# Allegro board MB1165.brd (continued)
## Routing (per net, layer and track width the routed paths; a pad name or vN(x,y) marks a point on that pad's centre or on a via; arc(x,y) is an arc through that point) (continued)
VBUS_FS1: length 209.7
  TOP w0.203: D5.B3 8.68,100.12 9.27,100.71 v1(9.27,101.47)
  TOP w0.381: CN13.1 5.36,98.4 v1(6.73,97.03)
  TOP w0.508: CN6.54 114.2,122.94 112.88,124.26 v1(111.89,124.26) ; v1(6.73,97.03) 6.73,97 7.24,96.49 C49.1 8.31,93.29 U11.1 ; v1(9.27,101.47) 10.16,102.36 10.16,102.87 v1(10.67,103.38) R100.1 ; D9.1 v1(25.91,81.03)
  L3_SIG w0.508: JP14.3 3.18,74.17 3.18,76.35 5.16,78.33 5.16,81.48 6.1,82.42 6.1,94.74 6.73,95.38 v1(6.73,97.03) 6.73,97.69 6.02,98.4 6.02,100.51 6.99,101.47 v1(9.27,101.47) ; v1(111.89,124.26) 111.89,126.75 110.62,128.02 v1(108.08,128.02) 107.95,127.89 107.95,127.13 108.97,126.11 108.97,123.95 106.43,121.41 98.98,121.41 96.84,119.27 60.69,119.27 58.8,121.16 48.51,121.16 44.7,117.35 44.7,112.52 36.96,104.78 36.96,103.48 32.79,99.31 26.42,99.31 24.64,101.09 22.35,101.09 19.68,103.76 11.05,103.76 v1(10.67,103.38)
  BOTTOM w0.508: JP14.3 5.84,71.5 8.94,71.5 10.54,73.1 10.54,77.72 13.21,80.39 14.61,80.39 15.24,81.03 v1(25.91,81.03) ; v1(108.08,128.02) R253.2
VBUS_FS2: length 125.7
  TOP w0.254: D6.B3 8.81,85.77 9.83,86.79 v1(9.83,87.76)
  TOP w0.381: 5.36,84.04 CN14.1
  TOP w0.508: D10.1 v1(26.03,78.99) ; v1(39.52,127.48) 39.05,127.01 39.05,126.56 36.22,123.72 26.09,123.72 v1(25.86,123.49) ; v1(6.1,81.15) 7.24,81.15 R126.1 7.37,82.55 5.87,84.04 5.36,84.04 ; SB14.1 v1(15.88,114.05)
  L3_SIG w0.508: v1(6.1,81.15) 7.24,82.3 7.24,83.95 8,84.71 8,85.09 9.83,86.92 v1(9.83,87.76)
  BOTTOM w0.508: v1(25.86,123.49) 25.86,122.5 21.84,118.49 17.48,118.49 15.88,116.89 v1(15.88,114.05) 14.73,112.9 14.73,110.49 11.81,107.57 10.67,107.57 9.91,106.81 9.91,87.83 v1(9.83,87.76) ; v1(26.03,78.99) 26.16,78.99 26.75,78.41 26.75,74.61 27.18,74.18 27.18,73.65 26.75,73.22 26.75,73.1 25.91,72.26 25.15,72.26 22.35,69.47 19.79,69.47 19.28,68.96 5.84,68.96 JP14.5 2.67,72.14 2.67,77.72 v1(6.1,81.15) ; R255.1 39.55,127.51 v1(39.52,127.48)
VBUS_HS: length 75.8
  TOP w0.203: D3.A1 7.75,116.13 v1(7.37,115.75)
  TOP w0.381: CN8.1 6.96,111.86 L2.2
  TOP w0.508: L2.2 v1(7.37,113.18) ; D8.1 v1(25.93,83.06)
  BOTTOM w0.508: v1(25.93,83.06) 14.22,83.06 9.27,78.11 9.27,75.06 8.26,74.04 5.84,74.04 JP14.1 4.57,77.98 7.16,80.56 7.16,82.63 5.97,83.82 5.97,100.58 7.37,101.98 v1(7.37,113.18) v1(7.37,115.75)
VDD_MCU: length 46.8
  TOP w0.381: v5(79.61,140.09) U4.G5 ; v5(81.21,135.29) U4.E10 ; U4.H5 v5(78.01,139.29) ; U4.L9 v5(75.61,136.09) ; U4.F4 v5(80.41,140.89) ; U4.E8 v5(81.21,136.89) U4.E9 ; U4.E7 v5(80.41,138.49) ; U4.L10 v5(75.61,135.29) ; U4.J11 v5(77.21,134.49) U4.K11 ; U4.L8 v5(76.41,136.89) ; U4.H11 v5(78.01,134.49) ; v5(75.61,138.49) U4.L7 ; U4.F5 v5(80.41,140.09) ; U4.J5 v5(77.22,139.29) ; U4.F11 v5(80.41,134.49) ; v5(79.61,134.49) U4.G11 ; U4.K5 v5(76.41,140.09)
  TOP w0.508: v1(88.77,132.08) 89.03,131.83 C26.2 ; C28.2 60.33,130.81 v1(60.2,130.68)
  BOTTOM w0.381: v5(86.11,135.66) 86.08,135.64 85.78,135.64 85.27,136.14 C133.1 ; v5(78.01,139.29) 78.17,139.45 C121.1 ; C111.1 81.66,143.76 v5(81.28,143.38) ; v5(76.41,136.89) 76.45,136.93 C127.1 ; C126.1 80.77,138.12 v5(80.41,138.49) ; v5(79.61,140.09) 79.11,140.59 C117.1 ; C135.1 72.64,135.38 72.14,134.87 v5(72.01,134.87) ; C125.1 81.92,137.59 v5(81.21,136.89) ; C107.2 86.49,149.1 v1(86.94,149.56) ; v5(81.21,135.29) 80.77,135.73 C131.1 ; v3(77.93,145.01) 77.93,144.88 77.9,144.86 77.9,144.58 78.02,144.47 78.02,144.23 C112.1 ; C129.1 72.64,137.8 v5(72.06,138.38) 72.62,138.94 C120.1 ; v1(85.88,137.85) 85.85,137.85 85.82,137.81 85.24,137.81 C124.1 ; C132.1 75.79,136.27 v5(75.61,136.09) ; v5(78.01,134.49) 78.26,134.24 C136.1 ; C134.1 78.77,135.33 v5(79.61,134.49) ; C128.1 75.31,138.19 v5(75.61,138.49) ; C119.1 85.05,140.54 85.43,140.54 v5(85.72,140.84)
  BOTTOM w0.508: JP2.2 61.09,150.57 ; JP2.2 60.12,149.61 ; JP2.2 62.05,149.61 ; JP2.2 61.09,148.64 ; 61.09,143.64 61.09,144.6 ; 61.09,143.64 61.93,143.64 ; 61.09,143.64 61.09,142.67 ; 61.09,143.64 60.25,143.64 ; 61.85,140.49 L7.1 ; L7.1 61.85,141.71 ; L7.1 61.2,141.1 ; 61.09,146.3 61.09,147.27 ; 61.09,146.3 61.09,145.34 ; 61.09,146.3 61.93,146.3 ; 61.09,146.3 60.25,146.3 ; C130.2 v1(59.82,137.41) ; C118.1 59.94,141.58 ; C118.1 60.43,141.1 ; C118.1 59.94,140.61
  vias: v1(60.2,139.95) v1(60.2,139.32) v1(60.96,139.95) v1(60.96,139.32) v1(61.72,139.95) v1(61.72,139.32)
VDDA: length 15.6
  TOP w0.381: v5(72.14,143.05) 72.14,143.01 72.26,142.89 U4.R1
  TOP w0.508: v3(68.07,143.64) 67.06,143.64 R33.1
  BOTTOM w0.381: v5(72.14,143.05) 72.52,142.67 C116.2
  BOTTOM w0.508: L7.2 TP9.1 C114.1 v3(68.07,143.64) 68.71,143.64 69.29,143.05 v5(72.14,143.05)
A0: length 136.3
  TOP w0.102: 78.84,107.95 77.47,106.58 77.47,105.81 U9.E2 ; v5(69.74,73.28) 69.74,73.52 69.22,74.03 U16.A3 ; U15.G8 91.83,71.77 v5(91.44,71.37)
  TOP w0.127: CN11.14 v3(103.38,109.78) ; v4(78.89,108.08) 78.84,108.03 78.84,107.95
  L3_SIG w0.102: v3(103.38,109.78) 102.9,109.3 101.35,109.3 98.48,106.43 80.17,106.43 78.89,107.71 v4(78.89,108.08) ; v5(91.44,71.37) 91.44,71.63 89.83,73.23 84.28,73.23 83.59,72.54 79.57,72.54 v1(79.29,72.82) 79.21,72.9 78.81,72.9 78.61,72.69 78.41,72.69 78.2,72.9 78,72.9 77.8,72.69 77.59,72.69 77.39,72.9 77.19,72.9 76.98,72.69 76.78,72.69 76.58,72.9 76.38,72.9 76.17,72.69 75.97,72.69 75.77,72.9 75.56,72.9 75.36,72.69 75.16,72.69 74.95,72.9 74.75,72.9 74.55,72.69 74.34,72.69 74.14,72.9 73.94,72.9 73.73,72.69 73.53,72.69 73.33,72.9 73.12,72.9 72.92,72.69 72.72,72.69 72.51,72.9 72.31,72.9 72.11,72.69 71.9,72.69 71.7,72.9 71.42,72.9 71.32,72.8 70.21,72.8 69.74,73.26 v5(69.74,73.28)
  BOTTOM w0.127: v3(103.38,109.78) 102.82,109.22 101.73,109.22 95.15,115.8 95.15,120.12 95.02,120.24 94.23,120.24 94.11,120.37 94.11,137.57 92.74,138.94 90.93,138.94 R236.2 ; v4(78.89,108.08) 78.89,105.13 79.88,104.14 79.88,101.6 80.52,100.97 81.92,100.97 82.82,100.06 82.82,99.7 82.8,99.69 82.8,99.64 80.8,97.64 80.8,94.65 80.53,94.39 80.53,76.06 79.5,75.03 79.5,74.14 79.29,73.93 v1(79.29,72.82)
A1: length 137.8
  TOP w0.102: v5(69.2,73.28) 69.2,73.29 U16.A4 ; 79.88,107.95 78.51,106.58 78.51,105.77 U9.D2 ; U15.G9 91.44,70.55 v5(91.44,70.48)
  TOP w0.127: CN11.12 v3(103.38,111.05) ; v4(80.26,108.64) 79.93,108.31 79.93,108 79.88,107.95
  L3_SIG w0.102: v4(80.26,108.64) 80.26,108.46 81.53,107.19 97.89,107.19 101.22,110.52 102.84,110.52 v3(103.38,111.05) ; v5(91.44,70.48) 91.01,70.91 91.01,71.52 89.6,72.93 84.49,72.93 83.77,72.21 80.49,72.21 v1(80.39,72.11) 80.29,72.11 80.26,72.14 79.5,72.14 79.25,72.39 69.96,72.39 69.2,73.15 v5(69.2,73.28)
  BOTTOM w0.127: v3(103.38,111.05) 103.38,110.95 102.9,110.46 101.83,110.46 96.06,116.23 96.06,121.28 94.87,122.48 94.87,139.48 93,141.35 91.69,141.35 R232.2 ; v4(80.26,108.64) 80.26,108.43 83.03,105.66 83.03,104.17 85.09,102.11 85.09,86.23 84.96,86.11 83.11,86.11 82.98,85.98 82.98,78.76 82.36,78.14 82.36,75.73 81.41,74.78 81.41,73.79 80.39,72.77 v1(80.39,72.11)
A2: length 134.8
  TOP w0.102: U15.F7 92.08,73.15 v5(91.44,73.15) ; 81.33,107.95 81.33,107.62 80.47,106.76 80.47,105.93 U9.C2 ; U16.A5 70.25,72.54 70.87,73.15 v5(70.89,73.15)
  TOP w0.127: v4(81.33,108.53) 81.33,107.95 ; CN11.8 v3(103.38,113.59)
  L3_SIG w0.102: v3(103.38,113.59) 102.44,112.65 101.65,112.65 96.95,107.95 81.92,107.95 v4(81.33,108.53) ; v5(70.89,73.15) 70.97,73.15 71.07,73.25 79.66,73.25 79.93,72.97 v1(81.41,72.97) 83.49,72.97 84.06,73.54 84.45,73.54 84.46,73.53 91.06,73.53 v5(91.44,73.15)
  BOTTOM w0.127: v3(103.38,113.59) 102.44,112.65 101.02,112.65 96.95,116.71 96.95,121.77 95.63,123.09 95.63,140.97 92.46,144.15 91.31,144.15 R230.2 ; v4(81.33,108.53) 81.33,108.51 83.92,105.92 83.92,104.36 85.85,102.43 85.85,85.85 83.74,83.74 83.74,78.41 83.44,78.11 83.44,75.56 83.12,75.25 82.42,75.25 81.79,74.62 81.79,73.41 81.41,73.03 v1(81.41,72.97)
A3: length 134.4
  TOP w0.102: 82.45,107.95 82.45,105.88 81.94,105.37 U9.A2 ; U16.B3 v5(68.29,74.41) ; v5(92.2,75.31) U15.F3
  TOP w0.127: v4(82.25,108.66) 82.45,108.46 82.45,107.95 ; v3(101.98,114.68) 101.8,114.86 CN11.5
  L3_SIG w0.102: v3(101.98,114.68) 101.85,114.68 96.77,109.6 83.97,109.6 83.41,109.04 82.6,109.04 82.25,108.69 v4(82.25,108.66) ; v5(68.29,74.41) 68.43,74.55 69.75,74.55 70.32,75.12 82.61,75.12 v1(82.93,74.8) 83.24,75.11 90.93,75.11 91.06,75.23 91.06,75.74 91.16,75.84 91.31,75.84 91.41,75.74 91.41,75.21 91.52,75.11 91.67,75.11 91.77,75.21 91.77,75.64 91.9,75.77 93.22,75.77 93.34,75.64 93.34,75.44 93.22,75.31 v5(92.2,75.31)
  BOTTOM w0.127: R226.2 95.63,145.92 97.03,144.53 97.03,133.4 98.17,132.26 98.17,123.44 98.45,123.16 98.45,117.35 101.12,114.68 v3(101.98,114.68) ; v1(82.93,74.8) 83.69,74.8 83.95,75.06 83.95,77.98 84.12,78.16 84.12,83.57 86.23,85.67 86.23,102.59 84.23,104.59 84.23,106.37 82.25,108.35 v4(82.25,108.66)
A4: length 138.9
  TOP w0.102: v5(92.24,76.96) 92.2,77 92.2,77.02 U15.G1 ; 81.79,107.95 81.79,106.93 81.43,106.58 81.43,105.89 U9.B2 ; v5(70.35,74.6) 70.35,74.55 70.23,74.44 70.23,73.15 69.98,72.9 68.3,72.9 U16.B4
  TOP w0.127: v4(82.25,109.58) 82.25,109.55 81.79,109.09 81.79,107.95 ; CN11.3 101.17,116.13 101.6,115.7 v3(101.93,115.7)
  L3_SIG w0.102: v5(92.24,76.96) 93.73,76.96 93.85,76.83 93.85,74.9 93.73,74.78 83.54,74.78 83.11,74.35 82.61,74.35 82.44,74.52 v1(82.36,74.52) 82.07,74.82 70.61,74.82 70.39,74.6 v5(70.35,74.6) ; v3(101.93,115.7) 100.1,115.7 83.49,110.49 v4(82.25,109.58)
  BOTTOM w0.127: v4(82.25,109.58) 82.68,109.14 82.68,108.46 82.96,108.18 85.17,105.97 85.17,104.19 86.74,102.62 86.74,85.5 84.51,83.26 84.51,78 84.33,77.82 84.33,74.85 83.64,74.17 82.72,74.17 v1(82.36,74.52) ; v3(101.93,115.7) 100.71,116.92 100.71,131.29 97.79,134.21 97.79,145.03 95.58,147.24 90.86,147.24 R223.2
A5: length 137.9
  TOP w0.102: v5(92.22,76.18) 92.2,76.2 92.2,76.23 U15.G2 ; U9.D3 78.31,104.97 78.31,106.76 79.5,107.95 ; U16.C3 v5(67.54,74.41)
  TOP w0.127: 79.5,107.95 79.5,108.71 80.19,109.4 v4(80.39,109.4) ; CN11.1 101.02,117.4 101.57,117.96 v3(101.57,118.31)
  L3_SIG w0.102: v3(101.57,118.31) 99.3,116.04 81.29,110.25 80.44,109.4 v4(80.39,109.4) ; v5(92.22,76.18) 93.38,76.18 93.5,76.3 93.5,76.46 93.38,76.58 91.76,76.58 91.66,76.48 91.66,76.25 91.56,76.15 91.36,76.15 91.26,76.25 91.26,76.46 91.13,76.58 90.95,76.58 90.83,76.46 90.83,76.2 90.7,76.07 90.37,76.07 90.25,75.95 90.25,75.82 90.37,75.69 90.65,75.69 90.78,75.56 90.78,75.44 90.65,75.31 84.56,75.31 84.18,75.69 v1(82.91,75.69) 82.65,75.44 70.31,75.44 69.75,74.88 68.01,74.88 v5(67.54,74.41)
  BOTTOM w0.127: v1(82.91,75.69) 82.91,78.14 83.36,78.6 83.36,83.92 85.47,86.03 85.47,102.27 83.54,104.2 83.54,105.69 81.28,107.95 80.87,108.36 80.87,108.92 v4(80.39,109.4) ; v3(101.57,118.31) 101.7,118.44 102.72,124.29 102.74,124.42 102.74,130.05 98.17,134.62 98.17,145.41 95.87,147.71 95.86,147.71 90.81,148.46 R221.2
A6: length 135.7
  TOP w0.102: U16.C4 v5(67.54,72.91) ; v5(91.44,74.42) 91.69,74.68 91.69,75.6 U15.G3 ; U9.C3 v4(80.41,104.87)
  TOP w0.127: CN10.5 52.78,114.86 v3(53.47,114.17)
  L3_SIG w0.102: v3(53.47,114.17) 53.98,114.17 54.48,113.67 69.72,113.67 78.52,104.87 v4(80.41,104.87) ; v5(91.44,74.42) 90.81,73.79 84.45,73.79 84.39,73.84 83.93,73.84 83.49,73.41 v1(80.33,73.41) 79.93,73.41 79.7,73.63 68.26,73.63 v5(67.54,72.91)
  BOTTOM w0.127: v1(80.33,73.41) 80.33,74.78 81.6,76.05 81.6,78.68 82.22,79.3 82.22,90.09 82.35,90.22 84.07,90.22 84.2,90.35 84.2,90.6 84.07,90.73 82.35,90.73 82.22,90.86 82.22,91.08 82.35,91.21 84.2,91.21 84.33,91.34 84.33,91.59 84.2,91.72 82.35,91.72 82.22,91.85 82.22,92.1 82.35,92.23 84.2,92.23 84.33,92.35 84.33,92.61 84.2,92.74 82.35,92.74 82.22,92.86 82.22,93.12 82.35,93.24 84.2,93.24 84.33,93.37 84.33,101.88 83.95,102.26 83.95,102.49 83.31,103.12 82.17,103.12 81.74,103.55 81.74,103.73 81.8,103.79 81.8,103.97 81.62,104.15 81.44,104.15 81.38,104.09 81.2,104.09 80.42,104.87 v4(80.41,104.87) ; R248.2 66.04,132.84 65.41,132.21 63.37,132.21 62.87,131.7 62.87,121.11 56.57,114.81 54.1,114.81 v3(53.47,114.17)
A7: length 137.4
  TOP w0.102: v5(90.32,74.42) 90.55,74.42 91.44,75.31 91.44,76.99 U15.H1 ; U16.D4 v5(66.79,72.91) ; U9.A3 v4(81.45,104.83)
  TOP w0.127: CN10.3 52.65,116.13 53.34,115.44 v3(53.47,115.44)
  L3_SIG w0.102: v4(81.45,104.83) 80.74,105.54 79.88,105.54 70.64,114.78 54.13,114.78 v3(53.47,115.44) ; v5(90.32,74.42) 90.32,74.12 90.27,74.07 84.56,74.07 84.45,74.17 83.82,74.17 83.36,73.71 81.07,73.71 v1(80.87,73.91) 80.84,73.94 69.6,73.94 69.49,73.84 67.72,73.84 v5(66.79,72.91)
  BOTTOM w0.127: R245.2 65.79,134.11 65.15,133.48 63.12,133.48 62.08,132.44 62.08,121.54 56.34,115.8 54.69,115.8 54.34,115.44 v3(53.47,115.44) ; v1(80.87,73.91) 80.87,74.77 81.98,75.89 81.98,78.3 82.6,78.92 82.6,86.55 82.73,86.68 84.3,86.68 84.43,86.81 84.43,87.11 84.3,87.24 82.73,87.24 82.6,87.37 82.6,87.66 82.73,87.78 84.58,87.78 84.71,87.91 84.71,88.16 84.58,88.29 82.75,88.29 82.63,88.42 82.63,88.67 82.75,88.8 84.58,88.8 84.71,88.93 84.71,89.18 84.58,89.31 82.75,89.31 82.63,89.43 82.63,89.69 82.75,89.81 84.58,89.81 84.71,89.94 84.71,101.95 84.45,102.21 84.45,102.36 83.19,103.63 82.91,103.63 81.71,104.83 v4(81.45,104.83)
A8: length 139.9
  TOP w0.102: U9.B6 81.41,101.87 v4(81.41,101.88) ; U16.H2 v5(63.04,75.16) ; v5(90.66,76.97) U15.H2
  TOP w0.127: v3(54.9,115.3) 54.91,115.32 54.99,115.32 55.8,116.13 CN10.4
  L3_SIG w0.102: v5(63.04,75.16) 63.04,75.69 63.37,76.02 63.37,78.74 64.9,80.26 v1(81.37,80.26) 81.37,81.31 81.5,81.43 81.74,81.43 81.86,81.31 81.86,80.92 81.99,80.8 82.22,80.8 82.32,80.9 82.32,81.31 82.44,81.43 82.61,81.43 82.73,81.31 82.73,80.9 82.83,80.8 83.03,80.8 83.13,80.9 83.13,81.31 83.25,81.43 83.42,81.43 83.54,81.31 83.54,80.9 83.64,80.8 83.85,80.8 83.95,80.9 83.95,81.31 84.07,81.43 84.23,81.43 84.35,81.31 84.35,80.9 84.45,80.8 84.66,80.8 84.76,80.9 84.76,81.31 84.88,81.43 85.05,81.43 85.17,81.31 85.17,80.9 85.27,80.8 85.47,80.8 85.57,80.9 85.57,81.31 85.69,81.43 85.86,81.43 85.98,81.31 85.98,80.9 86.08,80.8 86.33,80.8 86.46,80.92 86.46,81.31 86.59,81.43 86.74,81.43 86.87,81.31 86.87,80.29 87,80.16 87.86,80.16 87.96,80.26 87.96,80.72 88.06,80.82 88.27,80.82 88.37,80.72 88.37,80.26 88.47,80.16 89.87,80.16 90.27,79.76 90.27,77.65 90.66,77.26 v5(90.66,76.97) ; v4(81.41,101.88) 81.92,102.39 81.92,104.92 81.1,105.74 80.11,105.74 70.55,115.3 v3(54.9,115.3)
  BOTTOM w0.127: v3(54.9,115.3) 54.91,115.32 56.41,115.32 62.46,121.36 62.46,131.93 63.37,132.84 R249.2 ; v1(81.37,80.26) 81.37,94.09 81.56,94.28 81.56,95.96 81.69,96.09 83.44,96.09 83.57,96.22 83.57,96.47 83.44,96.6 81.84,96.6 81.71,96.72 81.71,96.98 81.84,97.1 83.44,97.1 83.57,97.23 83.57,97.49 83.44,97.61 82.42,97.61 82.3,97.74 82.3,97.99 82.42,98.12 83.44,98.12 83.57,98.25 83.57,100.2 82.18,101.59 82.18,102.02 81.33,102.87 80.85,102.87 80.72,103 80.72,103.45 80.59,103.58 80.34,103.58 80.21,103.45 80.21,102.46 80.34,102.34 81.28,102.34 81.41,102.21 v4(81.41,101.88)
A9: length 140.9
  TOP w0.102: v4(83.31,101.21) 82.07,101.21 U9.A6 ; v5(89.86,76.17) U15.J3 ; U16.H3 v5(63.04,74.41)
  TOP w0.127: CN10.18 v3(54.86,107.24)
  L3_SIG w0.102: v5(89.86,76.17) 89.86,76.42 90.22,76.78 90.22,77.29 89.92,77.6 89.92,79.68 89.79,79.81 86.56,79.81 86.46,79.91 86.46,80.37 86.36,80.47 86.15,80.47 86.05,80.37 86.05,79.82 85.93,79.71 85.76,79.71 85.64,79.82 85.64,80.37 85.52,80.49 85.36,80.49 85.24,80.37 85.24,79.88 85.12,79.76 84.95,79.76 84.83,79.88 84.83,80.37 84.71,80.49 84.54,80.49 84.42,80.37 84.42,79.62 84.31,79.5 84.14,79.5 84.02,79.62 84.02,80.37 83.9,80.49 83.73,80.49 83.61,80.37 83.61,79.62 83.49,79.5 83.32,79.5 83.21,79.62 83.21,80.37 83.09,80.49 82.92,80.49 82.8,80.37 82.8,79.63 82.67,79.5 82.45,79.5 82.32,79.63 82.32,80.37 82.19,80.49 81.97,80.49 81.84,80.37 81.84,79.76 81.71,79.63 v1(81.37,79.63) 64.9,79.63 63.75,78.49 63.75,76.01 63.43,75.69 63.43,74.8 v5(63.04,74.41) ; v3(54.86,107.24) 64.92,107.24 70.84,101.32 71.25,101.32 71.78,101.85 72.69,101.85 73.04,101.51 76.51,101.51 76.54,101.48 78.9,101.48 79.54,100.84 82.17,100.84 82.54,101.21 v4(83.31,101.21)
  BOTTOM w0.127: v3(54.86,107.24) 54.94,107.31 57.91,107.31 68.07,117.47 68.07,122.06 67.94,122.18 67.69,122.18 67.56,122.31 67.56,122.56 67.69,122.69 67.94,122.69 68.07,122.82 68.07,123.07 67.94,123.2 67.69,123.2 67.56,123.33 67.56,123.58 67.69,123.71 67.94,123.71 68.07,123.83 68.07,125.09 R261.2 ; v1(81.37,79.63) 81.37,79.64 81.84,80.11 81.84,93.52 81.97,93.65 83.82,93.65 83.95,93.78 83.95,94.03 83.82,94.16 82.07,94.16 81.94,94.28 81.94,94.54 82.07,94.67 83.82,94.67 83.95,94.79 83.95,95.05 83.82,95.17 82.07,95.17 81.94,95.3 81.94,95.55 82.07,95.68 83.82,95.68 83.95,95.81 83.95,101.73 83.82,101.85 82.98,101.85 82.85,101.73 82.85,101.33 82.98,101.21 v4(83.31,101.21)
A10: length 137.7
  TOP w0.102: v4(80.41,101.85) 79.93,101.37 U9.C6 ; v5(91.48,72.19) U15.G7 ; U16.H4 v5(63.04,72.91)
  TOP w0.127: CN10.6 55.42,114.86 v3(54.74,114.17)
  L3_SIG w0.102: v3(54.74,114.17) 70.74,114.17 79.65,105.26 80.57,105.26 80.8,105.03 80.8,102.25 v4(80.41,101.85) ; v5(91.48,72.19) 91.8,71.88 91.8,70.28 90.18,68.67 89.32,68.67 88.75,68.1 88.58,68.1 88.09,68.59 87.94,68.59 87.8,68.45 87.8,68.3 88.38,67.72 88.38,67.55 88.26,67.43 88.09,67.43 87.51,68.01 87.37,68.01 87.23,67.87 87.23,67.73 87.76,67.2 87.76,67.1 87.34,66.67 v1(79.38,66.67) 67.23,66.67 62.61,71.3 62.61,72.48 v5(63.04,72.91)
  BOTTOM w0.127: v3(54.74,114.17) 54.86,114.3 56.74,114.3 63.25,120.8 63.25,131.19 R251.2 ; v1(79.38,66.67) 79.88,67.18 79.88,74.87 80.91,75.9 80.91,94.22 81.18,94.49 81.18,97.43 83.19,99.44 83.19,100.15 81.99,101.35 80.92,101.35 v4(80.41,101.85)
A11: length 139
  TOP w0.102: U9.D6 78.36,101.92 v4(78.36,103.89) ; v5(90.66,70.57) U15.H9 ; U16.H5 v5(63.04,72.16)
  TOP w0.127: v3(53.34,113.16) 52.91,113.59 CN10.7
  L3_SIG w0.102: v5(63.04,72.16) 63.4,71.8 63.4,71.1 67.31,67.18 v1(78.61,67.18) 86.08,67.18 86.28,67.38 86.42,67.38 86.65,67.16 86.79,67.16 86.93,67.3 86.93,67.44 86.71,67.67 86.71,67.81 88.02,69.13 88.54,69.13 88.65,69.23 88.65,70.11 88.77,70.23 88.93,70.23 89.05,70.11 89.05,69.23 89.15,69.13 90.18,69.13 90.66,69.6 v5(90.66,70.57) ; v3(53.34,113.16) 53.98,112.52 53.98,112.14 54.48,111.63 55.56,111.63 55.67,111.73 55.67,111.91 55.77,112.01 55.97,112.01 56.07,111.91 56.07,111.73 56.17,111.63 56.38,111.63 56.48,111.73 56.48,111.91 56.58,112.01 56.78,112.01 56.89,111.91 56.89,111.73 56.99,111.63 57.19,111.63 57.29,111.73 57.29,111.91 57.39,112.01 57.6,112.01 57.7,111.91 57.7,111.73 57.8,111.63 58,111.63 58.1,111.73 58.1,111.91 58.21,112.01 58.41,112.01 58.51,111.91 58.51,111.73 58.61,111.63 58.82,111.63 58.92,111.73 58.92,111.91 59.02,112.01 59.22,112.01 59.32,111.91 59.32,111.73 59.43,111.63 59.63,111.63 59.73,111.73 59.73,111.91 59.83,112.01 60.03,112.01 60.14,111.91 60.14,111.73 60.24,111.63 60.44,111.63 60.54,111.73 60.54,111.91 60.64,112.01 60.85,112.01 60.95,111.91 60.95,111.73 61.05,111.63 61.25,111.63 61.36,111.73 61.36,111.91 61.46,112.01 61.66,112.01 61.76,111.91 61.76,111.73 61.86,111.63 62.07,111.63 62.17,111.73 62.17,111.91 62.27,112.01 62.47,112.01 62.57,111.91 62.57,111.73 62.68,111.63 71.25,111.63 78.36,104.52 v4(78.36,103.89)
  BOTTOM w0.127: R250.2 63.65,128.93 63.65,120.62 56.69,113.67 53.85,113.67 v3(53.34,113.16) ; v1(78.61,67.18) 79.5,68.07 79.5,71.98 78.49,73 78.49,75.09 79.76,76.36 79.76,94.82 80.01,95.07 80.01,98.68 78.99,99.69 78.99,100.84 78.87,100.97 78.87,103.38 v4(78.36,103.89)
A12: length 120.9
  TOP w0.102: U9.B7 v4(81.41,99.87) ; v5(63.79,74.41) U16.G3
  TOP w0.127: CN10.33 53.29,97.08 v3(53.42,97.21)
  L3_SIG w0.102: v4(81.41,99.87) 81.41,99.87 81.41,98.68 79.78,97.05 75.41,97.05 75.08,97.38 55.68,97.38 55.02,96.72 53.9,96.72 v3(53.42,97.21)
  BOTTOM w0.127: R269.2 73.66,122.17 73.66,115.19 56.26,97.79 54,97.79 v3(53.42,97.21) ; v5(63.79,74.41) 64.77,75.39 68.72,75.39 69.11,75.78 69.11,77.65 67.84,78.92 67.84,82.4 66.42,83.82 66.42,100.33 70.99,104.9 74.68,104.9 74.93,105.16 78.52,105.16 79.63,104.05 79.63,101.47 81.23,99.87 v4(81.41,99.87)
A13: length 125.2
  TOP w0.102: U9.A7 v4(82.41,99.87) ; v5(63.79,72.91) U16.G4
  TOP w0.127: CN10.34 55.07,97.08 v3(54.86,97.28)
  L3_SIG w0.102: v3(54.86,97.28) 55.07,97.28 55.5,97.71 75.26,97.71 75.59,97.38 79.48,97.38 80.9,98.81 80.9,99.92 81.31,100.33 81.95,100.33 v4(82.41,99.87)
  BOTTOM w0.127: v4(82.41,99.87) 81.96,99.42 80.16,99.42 79.88,99.69 79.88,100.33 79.12,101.09 79.12,103.89 78.49,104.52 75.5,104.52 74.99,104.01 71.37,104.01 67.18,99.82 67.18,84.38 68.96,82.6 68.96,79.68 70,78.64 70,75.59 69.22,74.8 66.12,74.8 64.72,73.41 64.29,73.41 v5(63.79,72.91) ; R257.2 74.68,125.09 74.68,123.96 74.42,123.7 74.42,121.79 74.04,121.41 74.04,114.81 56.44,97.21 54.94,97.21 v3(54.86,97.28)
A14: length 134.8
  TOP w0.102: v4(79.48,99.95) 79.49,99.95 U9.C7 ; v5(89.79,74.42) 89.79,73.04 U15.J7 ; U16.F3 v5(64.54,74.41)
  TOP w0.127: CN10.28 v3(54.86,100.89)
  L3_SIG w0.102: v4(79.48,99.95) 78.84,99.31 78.21,99.31 77.57,98.68 68.2,98.68 65.99,100.89 65.02,100.89 64.92,100.79 64.92,100.05 64.82,99.95 64.62,99.95 64.51,100.05 64.51,100.79 64.41,100.89 64.21,100.89 64.11,100.79 64.11,100.05 64.01,99.95 63.8,99.95 63.7,100.05 63.7,100.79 63.6,100.89 63.4,100.89 63.3,100.79 63.3,100.05 63.19,99.95 62.99,99.95 62.89,100.05 62.89,100.79 62.79,100.89 62.58,100.89 62.48,100.79 62.48,100.05 62.38,99.95 62.18,99.95 62.08,100.05 62.08,100.79 61.97,100.89 61.77,100.89 61.67,100.79 61.67,100.05 61.57,99.95 61.37,99.95 61.26,100.05 61.26,100.79 61.16,100.89 60.96,100.89 60.86,100.79 60.86,100.05 60.76,99.95 60.55,99.95 60.45,100.05 60.45,100.79 60.35,100.89 60.15,100.89 60.04,100.79 60.04,100.05 59.94,99.95 59.74,99.95 59.64,100.05 59.64,100.79 59.54,100.89 59.33,100.89 59.23,100.79 59.23,100.05 59.13,99.95 58.93,99.95 58.83,100.05 58.83,100.79 58.72,100.89 58.52,100.89 58.42,100.79 58.42,100.05 58.32,99.95 58.11,99.95 58.01,100.05 58.01,100.79 57.91,100.89 57.71,100.89 57.61,100.79 57.61,100.05 57.5,99.95 57.3,99.95 57.2,100.05 57.2,100.79 57.1,100.89 56.89,100.89 56.79,100.79 56.79,100.02 56.67,99.9 56.51,99.9 56.39,100.02 56.39,100.79 56.29,100.89 56.08,100.89 55.98,100.79 55.98,100.04 55.86,99.92 55.69,99.92 55.57,100.04 55.57,100.79 55.47,100.89 v3(54.86,100.89) ; v5(89.79,74.42) 84.44,74.42 84.39,74.47 83.7,74.47 83.24,74.02 82.07,74.02 81.94,74.14 81.94,74.39 81.83,74.5 81.67,74.5 81.56,74.39 81.56,74.24 81.43,74.12 81.28,74.12 81.15,74.24 81.15,74.37 81.03,74.5 80.5,74.5 80.4,74.4 80.4,74.35 80.3,74.24 80.1,74.24 80,74.35 80,74.4 79.89,74.5 79.09,74.5 v1(78.98,74.39) 70.84,74.39 70.7,74.24 69.35,74.24 69.15,74.04 65.02,74.04 64.65,74.41 v5(64.54,74.41)
  BOTTOM w0.127: v4(79.48,99.95) 79.48,99.72 80.39,98.81 80.39,94.79 80.14,94.54 80.14,76.2 78.98,75.04 v1(78.98,74.39) ; v3(54.86,100.89) 54.94,100.97 57.66,100.97 72.49,115.8 72.49,120.11 72.39,120.21 R270.2
A15: length 137.9
  TOP w0.102: U16.F4 v5(64.54,72.91) ; v5(90.66,71.37) U15.H8 ; v4(78.36,99.83) 78.37,99.83 78.91,100.37 U9.D7
  TOP w0.127: CN10.25 v3(53.42,102.16)
  L3_SIG w0.102: v4(78.36,99.83) 77.58,99.06 68.4,99.06 65.99,101.47 65.5,101.47 65.4,101.57 65.4,102.16 65.3,102.26 65.1,102.26 64.99,102.16 64.99,101.57 64.89,101.47 64.69,101.47 64.59,101.57 64.59,102.16 64.49,102.26 64.28,102.26 64.18,102.16 64.18,101.57 64.08,101.47 63.88,101.47 63.78,101.57 63.78,102.16 63.67,102.26 63.47,102.26 63.37,102.16 63.37,101.57 63.27,101.47 63.06,101.47 62.96,101.57 62.96,102.16 62.86,102.26 62.66,102.26 62.56,102.16 62.56,101.57 62.45,101.47 62.25,101.47 62.15,101.57 62.15,102.16 62.05,102.26 61.84,102.26 61.74,102.16 61.74,101.57 61.64,101.47 61.44,101.47 61.34,101.57 61.34,102.16 61.24,102.26 61.03,102.26 60.93,102.16 60.93,101.57 60.83,101.47 60.63,101.47 60.52,101.57 60.52,102.16 60.42,102.26 60.22,102.26 60.12,102.16 60.12,101.57 60.02,101.47 59.81,101.47 59.71,101.57 59.71,102.16 59.61,102.26 59.41,102.26 59.3,102.16 59.3,101.57 59.2,101.47 59,101.47 58.9,101.57 58.9,102.16 58.8,102.26 58.59,102.26 58.49,102.16 58.49,101.57 58.39,101.47 58.19,101.47 58.09,101.57 58.09,102.16 57.98,102.26 57.78,102.26 57.68,102.16 57.68,101.57 57.58,101.47 57.37,101.47 57.27,101.57 57.27,102.16 57.17,102.26 56.97,102.26 56.87,102.16 56.87,101.57 56.76,101.47 56.56,101.47 56.46,101.57 56.46,102.16 56.36,102.26 56.16,102.26 56.05,102.16 56.05,101.57 55.95,101.47 54.1,101.47 v3(53.42,102.16) ; v5(64.54,72.91) 64.93,72.52 67.69,72.52 69.37,72.52 69.88,72.01 78.74,72.01 78.94,71.81 v1(78.99,71.81) 79.12,71.68 80.7,71.68 80.92,71.91 84.01,71.91 84.83,72.73 89.36,72.73 89.48,72.6 89.48,71.5 89.61,71.37 89.84,71.37 89.97,71.5 89.97,71.6 90.09,71.73 90.3,71.73 90.53,71.5 90.53,71.49 90.65,71.37 v5(90.66,71.37)
  BOTTOM w0.127: v1(78.99,71.81) 78.11,72.69 78.11,75.25 79.38,76.52 79.38,93.85 78.74,94.49 78.74,99.06 78.36,99.44 v4(78.36,99.83) ; v3(53.42,102.16) 54.13,102.87 57.84,102.87 71.12,116.15 71.12,120.52 71.5,120.9 71.5,124.11 71.88,124.49 71.88,125.09 R259.2
A16: length 119.5
  TOP w0.102: U9.E7 77.42,99.88 v4(77.42,99.83) ; v5(65.29,72.91) U16.E4
  TOP w0.127: v3(53.39,104.65) 53.34,104.7 CN10.21
  L3_SIG w0.102: v3(53.39,104.65) 53.47,104.65 54.1,104.01 64.72,104.01 68.91,99.82 77.4,99.82 v4(77.42,99.83)
  BOTTOM w0.127: v4(77.42,99.83) 77.42,100.91 78.11,101.6 78.11,102.74 77.82,103.03 77.82,103.04 77.48,103.38 73.53,103.38 73.41,103.25 71.79,103.25 67.94,99.41 67.94,86.46 69.98,84.43 69.98,79.86 71.45,78.38 71.45,72.87 71.32,72.75 70.88,72.75 70.75,72.62 70.75,71.42 70.63,71.3 70.37,71.3 70.25,71.42 70.25,72.75 70.12,72.87 69.87,72.87 69.74,72.75 69.74,71.78 69.61,71.65 69.36,71.65 69.23,71.78 69.23,72.75 69.1,72.87 68.73,72.87 68.61,72.75 68.61,71.45 68.48,71.32 68.17,71.32 68.05,71.45 68.05,72.4 67.92,72.53 66.47,72.53 66.34,72.4 66.34,71.6 66.22,71.48 65.94,71.48 65.81,71.6 65.81,72.77 65.67,72.91 v5(65.29,72.91) ; v3(53.39,104.65) 53.39,104.67 54.13,105.41 57.99,105.41 69.6,117.02 69.6,125.37 69.82,125.6 R260.1
A17: length 121.6
  TOP w0.102: v5(66.79,74.41) U16.D3 ; v4(78.46,100.84) 79.02,100.84 79.29,101.11 79.29,102.74 79.53,102.97 79.53,103.68 79.76,103.91 80.44,103.91 80.9,104.37 U9.B3
  TOP w0.127: CN10.23 v3(53.42,103.43)
  L3_SIG w0.102: v3(53.42,103.43) 54.1,102.74 65.38,102.74 68.68,99.44 77.68,99.44 77.97,99.73 77.97,100.34 v4(78.46,100.84)
  BOTTOM w0.127: v4(78.46,100.84) 78.61,100.99 78.61,103.07 78.2,103.48 78.19,103.48 77.85,103.82 77.85,104.14 77.71,104.28 75.7,104.28 75.06,103.63 71.63,103.63 67.56,99.57 67.56,85.61 67.69,85.49 68.2,85.49 68.33,85.36 68.33,85.11 68.2,84.98 67.69,84.98 67.56,84.85 67.56,84.56 67.69,84.43 69.39,84.43 69.52,84.3 69.52,79.68 70.38,78.82 70.38,78.46 70.51,78.33 70.92,78.33 71.04,78.21 71.04,78 70.92,77.88 70.51,77.88 70.38,77.75 70.38,77.47 70.51,77.34 70.84,77.34 70.97,77.22 70.97,76.96 70.84,76.83 70.51,76.83 70.38,76.71 70.38,76.45 70.51,76.33 70.84,76.33 70.97,76.2 70.97,75.95 70.84,75.82 70.51,75.82 70.38,75.69 70.38,75.44 70.51,75.31 70.84,75.31 70.97,75.18 70.97,73.66 70.84,73.53 70.07,73.53 69.94,73.66 69.94,74.47 69.82,74.6 69.56,74.6 69.44,74.47 69.44,73.81 69.31,73.69 69.05,73.69 68.93,73.81 68.93,73.91 68.8,74.04 68.55,74.04 68.42,73.91 68.42,73.48 68.29,73.36 68.04,73.36 67.91,73.48 67.91,73.91 67.78,74.04 67.53,74.04 67.4,73.91 67.4,73.48 67.28,73.36 66.57,73.36 66.45,73.48 66.45,74.28 66.57,74.41 v5(66.79,74.41) ; v3(53.42,103.43) 54,104.01 57.78,104.01 70.36,116.59 70.36,121.67 R271.2
A18: length 127.4
  TOP w0.102: v5(62.23,74.17) 62.23,75.17 62.59,75.54 U16.H1 ; U9.C4 79.91,102.91 79.53,102.53 79.53,101.07 79.76,100.84 80.14,100.84 80.39,100.58 v4(80.39,99.85)
  TOP w0.127: CN10.31 v3(53.42,98.35)
  L3_SIG w0.102: v4(80.39,99.85) 80.39,99.05 79.57,98.22 55.45,98.22 55.02,97.79 53.98,97.79 v3(53.42,98.35)
  BOTTOM w0.127: v3(53.42,98.35) 54.13,99.06 56.36,99.06 72.89,115.59 72.89,123.79 73.28,124.18 73.28,125.09 R258.2 ; v4(80.39,99.85) 80.39,100.33 79.38,101.35 79.38,103.98 78.56,104.79 75.2,104.79 74.84,104.43 71.16,104.43 66.8,100.08 66.8,84.12 68.33,82.6 68.33,79.04 69.62,77.75 69.62,75.75 68.98,75.11 65.94,75.11 64.62,73.79 62.61,73.79 v5(62.23,74.17)
A19: length 130.8
  TOP w0.102: v5(63.79,75.16) U16.G2 ; U9.D5 78.91,102.83 79.29,103.21 79.29,103.9 79.53,104.14 79.53,106.53 v4(80.08,107.08)
  TOP w0.127: v3(91.69,139.45) 91.44,139.19 R37.2 ; CN11.13 v3(101.98,109.78)
  L3_SIG w0.102: v4(80.08,107.08) 80.35,106.81 98.17,106.81 101.14,109.78 v3(101.98,109.78)
  BOTTOM w0.127: R234.2 91.69,140.08 v3(91.69,139.45) 92.84,139.45 94.49,137.79 94.49,121.77 94.61,121.64 95.12,121.64 95.25,121.51 95.25,121.26 95.12,121.13 94.61,121.13 94.49,121.01 94.49,120.75 94.61,120.62 95.48,120.62 95.61,120.5 95.61,116.03 101.85,109.78 v3(101.98,109.78) ; v4(80.08,107.08) 79.5,107.65 79.5,108.08 78.99,108.58 73.53,108.58 65.46,100.51 65.46,90.11 65.33,89.98 63.96,89.98 63.83,89.86 63.83,89.6 63.96,89.48 65.33,89.48 65.46,89.35 65.46,89.1 65.33,88.97 63.91,88.97 63.78,88.84 63.78,88.59 63.91,88.46 65.33,88.46 65.46,88.33 65.46,88.08 65.33,87.95 63.86,87.95 63.73,87.83 63.73,87.57 63.86,87.44 65.33,87.44 65.46,87.32 65.46,87.06 65.33,86.94 63.86,86.94 63.73,86.81 63.73,86.56 63.86,86.43 65.33,86.43 65.46,86.3 65.46,86.05 65.33,85.92 63.86,85.92 63.73,85.79 63.73,85.54 63.86,85.41 65.02,85.41 65.15,85.29 65.15,85.03 65.02,84.9 63.78,84.9 63.65,84.78 63.65,75.3 v5(63.79,75.16)
A20: length 133
  TOP w0.102: U16.H6 v5(63.04,71.41) ; U9.D4 78.91,103.83 79.3,104.22 79.3,106.98 80.26,107.95 80.39,107.95
  TOP w0.127: CN11.11 v3(101.98,111.05) ; 80.39,107.95 80.87,108.43 80.87,109.07 v4(81.36,109.55) ; v3(91.95,143.38) R35.2
  L3_SIG w0.102: v3(101.98,111.05) 101.02,111.05 97.54,107.57 81.66,107.57 80.85,108.38 80.85,109.04 v4(81.36,109.55)
  BOTTOM w0.127: v5(63.04,71.41) 62.56,71.89 62.56,71.91 61.24,73.23 61.24,76 61.37,76.12 62.74,76.12 62.87,76.25 62.87,90.86 62.99,90.98 64.45,90.98 64.57,91.11 64.57,91.36 64.45,91.49 62.94,91.49 62.81,91.62 62.81,91.87 62.94,92 64.45,92 64.57,92.13 64.57,92.38 64.45,92.51 63.04,92.51 62.92,92.63 62.92,92.89 63.04,93.01 64.45,93.01 64.57,93.14 64.57,100.86 73.83,110.11 80.9,110.11 81.36,109.65 v4(81.36,109.55) ; v3(101.98,111.05) 101.96,111.05 96.49,116.51 96.49,121.59 95.25,122.83 95.25,139.64 93.6,141.29 93.6,141.73 v3(91.95,143.38) 91.82,143.51 R231.2
A21: length 77.8
  TOP w0.102: U9.C5 80.53,102.99 81.07,102.99 81.08,103 81.74,103 81.75,102.99 82.67,102.99 83.57,103.89 83.57,107.95
  TOP w0.127: v4(83.19,109.52) 83.19,109.22 83.57,108.84 83.57,107.95 ; v3(103.5,115.57) 103.66,115.57 104.22,116.13 CN11.4 ; R32.2 91.63,146.75 v3(93.34,146.75) 93.6,147 93.6,147.32 R24.2
  L3_SIG w0.102: v4(83.19,109.52) 83.26,109.6 83.31,109.6 83.69,109.98 96.42,109.98 101.6,115.16 103.1,115.16 v3(103.5,115.57)
  BOTTOM w0.127: v3(103.5,115.57) 103.12,115.19 101.27,115.19 100.2,116.26 100.2,130.96 97.41,133.76 97.41,144.78 95.5,146.69 93.41,146.69 v3(93.34,146.75)
A22: length 71.7
  TOP w0.102: 84.61,107.95 84.61,106.02 84.2,105.61 84.2,100.71 82.4,98.91 81.37,98.91 U9.B8
  TOP w0.127: 84.61,107.95 v4(84.61,108.48) ; v1(91.82,144.65) R34.2 ; CN11.7 v3(101.98,113.59)
  L3_SIG w0.102: v3(101.98,113.59) 96.88,108.48 v4(84.61,108.48)
  BOTTOM w0.127: v1(91.82,144.65) 92.2,145.03 R229.2 96.65,141.86 96.65,132.97 97.66,131.95 97.66,123.19 98.04,122.81 98.04,117.09 101.55,113.59 v3(101.98,113.59)
A23: length 72.9
  TOP w0.102: U9.C8 80.68,98.6 82.47,98.6 84.66,100.79 v4(84.66,104.85)
  TOP w0.127: R39.2 92.71,137.29 92.08,137.92 v3(91.44,137.92) R38.2 ; CN11.16 v3(103.38,108.51)
  L3_SIG w0.102: v3(103.38,108.51) 102.9,108.99 101.63,108.99 97.49,104.85 v4(84.66,104.85)
  BOTTOM w0.127: v3(103.38,108.51) 102.77,107.9 101.7,107.9 94.18,115.42 94.18,119.3 94.06,119.43 93.47,119.43 93.34,119.56 93.34,137.16 92.58,137.92 v3(91.44,137.92)
AIN_1: length 3.8
  TOP w0.127: R170.2 R169.2 40.13,28.03 39.72,28.44 U21.10
BOOT0: length 88.2
  TOP w0.127: U4.E6 v5(81.21,139.29) ; v1(52.4,152.96) 52.32,153.03 52.32,164.97 51.18,166.12 R3.1
  L3_SIG w0.102: v1(52.4,152.96) 52.45,152.91 64.01,152.91 67.94,148.97 71.5,148.97 73.48,146.99 75.9,146.99 76.81,146.08 76.81,143.79 77.55,143.05 78.23,143.05 78.89,142.39 78.89,139.37 79.38,138.89 80.87,138.89 81.21,139.22 v5(81.21,139.29) 81.21,139.52 80.77,139.95 80.77,140.95 81.06,141.24 82.11,141.24 82.45,141.59 82.45,141.83 82.66,142.04 82.91,142.04 84.1,143.23 84.1,145.34 85.84,147.08 90.44,147.08 91.82,148.46 93.22,148.46 94.49,149.73 100.58,149.73 JP1.2
CAMERA_CLK: length 8.9
  TOP w0.203: CN4.20 151.51,147.69 151.25,147.96 v1(150.87,147.96) ; X3.3 145.23,148.08 v1(148.08,148.08)
  BOTTOM w0.203: v1(148.08,148.08) 150.74,148.08 v1(150.87,147.96)
D0: length 145.3
  TOP w0.102: v5(85.06,71.37) U15.R8 ; U9.E3 77.3,104.98 71.96,104.98 71.88,104.9 ; v5(68.29,70.9) 67.92,71.28 U16.B6
  TOP w0.127: 71.88,104.9 70.36,103.38 70.36,95.38 v3(70.87,94.87) ; CN10.39 52.78,93.27 v3(53.47,92.58)
  L3_SIG w0.102: v5(85.06,71.37) 84.66,70.97 81.61,70.97 81.15,70.51 76.61,70.51 76.38,70.28 v1(76.33,70.28) 76.05,70.28 75.72,70.61 69.47,70.61 69.04,71.04 68.42,71.04 68.29,70.92 v5(68.29,70.9) ; v3(53.47,92.58) 54.51,92.58 54.86,92.94 55.09,92.94 55.19,93.04 55.19,93.34 55.3,93.45 55.5,93.45 55.6,93.34 55.6,93.04 55.7,92.94 55.91,92.94 56.01,93.04 56.01,93.34 56.11,93.45 56.31,93.45 56.41,93.34 56.41,93.04 56.52,92.94 56.72,92.94 56.82,93.04 56.82,93.34 56.92,93.45 57.12,93.45 57.23,93.34 57.23,93.04 57.33,92.94 57.53,92.94 57.63,93.04 57.63,93.34 57.73,93.45 57.94,93.45 58.04,93.34 58.04,93.04 58.14,92.94 58.34,92.94 58.45,93.04 58.45,93.34 58.55,93.45 58.75,93.45 58.85,93.34 58.85,93.04 58.95,92.94 59.16,92.94 59.26,93.04 59.26,93.34 59.36,93.45 59.56,93.45 59.66,93.34 59.66,93.04 59.77,92.94 59.97,92.94 60.07,93.04 60.07,93.34 60.17,93.45 60.38,93.45 60.48,93.34 60.48,93.04 60.58,92.94 60.78,92.94 60.88,93.04 60.88,93.34 60.99,93.45 61.19,93.45 61.29,93.34 61.29,93.04 61.39,92.94 61.59,92.94 61.7,93.04 61.7,93.34 61.8,93.45 62,93.45 62.1,93.34 62.1,93.04 62.2,92.94 62.41,92.94 62.51,93.04 62.51,93.34 62.61,93.45 62.81,93.45 62.92,93.34 62.92,93.04 63.02,92.94 63.22,92.94 63.32,93.04 63.32,93.34 63.42,93.45 63.63,93.45 63.73,93.34 63.73,93.04 63.83,92.94 64.03,92.94 64.14,93.04 64.14,93.34 64.24,93.45 64.44,93.45 64.54,93.34 64.54,93.04 64.64,92.94 64.85,92.94 64.95,93.04 64.95,93.34 65.05,93.45 65.25,93.45 65.35,93.34 65.35,93.04 65.46,92.94 65.66,92.94 65.76,93.04 65.76,93.34 65.86,93.45 66.07,93.45 66.17,93.34 66.17,93.04 66.27,92.94 66.47,92.94 66.57,93.04 66.57,93.34 66.67,93.45 66.88,93.45 66.98,93.34 66.98,93.04 67.08,92.94 67.28,92.94 67.39,93.04 67.39,93.34 67.49,93.45 67.69,93.45 67.79,93.34 67.79,93.04 67.89,92.94 68.1,92.94 68.2,93.04 68.2,93.34 68.3,93.45 68.5,93.45 68.61,93.34 68.61,93.04 68.71,92.94 68.91,92.94 69.01,93.04 69.01,93.34 69.11,93.45 69.32,93.45 69.42,93.34 69.42,93.04 69.52,92.94 69.72,92.94 69.82,93.04 69.82,93.34 69.93,93.45 70.13,93.45 70.23,93.34 70.23,93.04 70.36,92.91 70.74,92.91 70.87,93.04 v3(70.87,94.87)
  BOTTOM w0.127: R268.2 76.45,114.17 56.9,94.61 56.39,94.61 54.36,92.58 v3(53.47,92.58) ; v3(70.87,94.87) 70.87,91.54 70.99,91.41 75.25,91.41 75.37,91.29 75.37,77.07 75.25,76.94 75.18,76.94 75.06,76.82 75.06,76.56 75.18,76.43 75.25,76.43 75.37,76.31 75.37,76.05 75.25,75.93 75.18,75.93 75.06,75.8 75.06,75.55 75.18,75.42 75.25,75.42 75.37,75.29 75.37,75.04 75.25,74.91 75.18,74.91 75.06,74.78 75.06,74.53 75.18,74.4 75.25,74.4 75.37,74.28 75.37,74.02 75.25,73.89 75.18,73.89 75.06,73.77 75.06,73.51 75.18,73.39 75.25,73.39 75.37,73.26 75.37,73.01 75.25,72.88 75.18,72.88 75.06,72.75 75.06,72.5 75.18,72.37 75.25,72.37 75.37,72.24 75.37,71.99 75.25,71.86 75.18,71.86 75.06,71.74 75.06,71.48 75.18,71.35 75.25,71.35 75.37,71.23 75.37,70.97 75.25,70.85 75.18,70.85 75.06,70.72 75.06,70.47 75.18,70.34 76.27,70.34 v1(76.33,70.28)
D1: length 144.8
  TOP w0.102: 71.88,103.12 73.13,104.37 U9.H3 ; v5(86.66,72.17) U15.N7 ; U16.C5 v5(67.54,72.16)
  TOP w0.127: v3(70.87,95.76) 70.87,100.63 71.5,101.27 71.5,102.74 71.88,103.12 ; v3(54.91,94.95) 55.35,94.95 55.75,94.54 CN10.38
  L3_SIG w0.102: v5(86.66,72.17) 86.26,71.77 84.85,71.77 84.35,71.27 81.46,71.27 81,70.82 76.5,70.82 v1(76.33,70.99) 75.28,70.99 75.13,71.15 74.87,71.15 74.72,70.99 74.47,70.99 74.31,71.15 74.06,71.15 73.91,70.99 73.65,70.99 73.5,71.15 73.25,71.15 73.09,70.99 72.84,70.99 72.69,71.15 72.43,71.15 72.28,70.99 72.03,70.99 71.88,71.15 71.62,71.15 71.47,70.99 70.87,70.99 70.74,71.12 70.74,71.51 70.61,71.64 70.36,71.64 70.23,71.51 70.23,71.22 70.1,71.09 69.82,71.09 69.7,71.22 69.7,71.75 69.29,72.16 68.35,72.16 68.22,72.03 68.22,71.81 68.1,71.68 67.92,71.68 67.79,71.81 67.79,72.03 67.67,72.16 v5(67.54,72.16) ; v3(54.91,94.95) 55.14,94.95 55.27,94.82 55.27,94.67 55.4,94.54 55.61,94.54 55.73,94.67 55.73,94.95 55.85,95.07 56.02,95.07 56.14,94.95 56.14,93.88 56.24,93.78 56.44,93.78 56.55,93.88 56.55,95 56.66,95.12 56.83,95.12 56.95,95 56.95,93.88 57.05,93.78 70.26,93.78 70.38,93.9 70.38,95.63 70.51,95.76 v3(70.87,95.76)
  BOTTOM w0.127: R256.2 75.92,125.2 75.92,114.28 56.76,95.12 55.09,95.12 v3(54.91,94.95) ; v1(76.33,70.99) 75.95,70.99 75.76,71.18 75.76,91.67 75.63,91.8 75.5,91.8 75.37,91.92 75.37,92.08 75.25,92.2 74.99,92.2 74.87,92.08 74.87,91.92 74.74,91.8 74.49,91.8 74.36,91.92 74.36,93.12 74.23,93.24 73.98,93.24 73.85,93.12 73.85,91.92 73.72,91.8 73.47,91.8 73.34,91.92 73.34,94.13 73.22,94.26 72.96,94.26 72.83,94.13 72.83,91.92 72.71,91.8 72.45,91.8 72.33,91.92 72.33,95.15 72.2,95.28 71.95,95.28 71.82,95.15 71.82,91.92 71.69,91.8 71.4,91.8 71.27,91.92 71.27,94.49 71.37,94.59 71.37,95.99 71.25,96.11 70.99,96.11 70.87,95.99 v3(70.87,95.76)
D2: length 134.8
  TOP w0.102: v5(67.54,70.9) 67.16,71.28 U16.C6 ; U9.E4 v4(77.41,103.87) ; v5(85.06,70.57) U15.R9
  TOP w0.127: CN11.31 v3(101.98,98.35)
  L3_SIG w0.102: v5(85.06,70.57) 85.06,69.98 84.93,69.85 84.63,69.85 84.51,69.98 84.51,70.38 84.4,70.48 84.2,70.48 84.1,70.38 84.1,69.95 84,69.85 83.79,69.85 83.69,69.95 83.69,70.38 83.59,70.48 83.39,70.48 83.29,70.38 83.29,69.95 83.19,69.85 82.98,69.85 82.88,69.95 82.88,70.39 82.76,70.51 82.59,70.51 82.47,70.39 82.47,69.95 82.37,69.85 82.17,69.85 82.07,69.95 82.07,70.44 81.95,70.56 81.78,70.56 81.66,70.44 81.66,69.95 81.56,69.85 v1(78.87,69.85) 75.39,69.85 75.01,70.23 68.21,70.23 v5(67.54,70.9) ; v4(77.41,103.87) 77.41,103.49 79.76,101.14 81.84,101.14 82.3,101.6 84.79,101.6 84.89,101.5 84.89,99.52 84.99,99.42 85.19,99.42 85.3,99.52 85.3,101.5 85.4,101.6 85.6,101.6 85.7,101.5 85.7,99.52 85.8,99.42 86.01,99.42 86.11,99.52 86.11,101.35 86.24,101.47 86.66,101.47 86.79,101.35 86.79,99.52 86.92,99.39 100.86,99.39 101.9,98.35 v3(101.98,98.35)
  BOTTOM w0.127: v3(101.98,98.35) 101.96,98.35 87.38,112.93 87.38,121.67 87.12,121.92 85.79,121.92 85.34,122.36 85.34,123.95 85.85,124.46 85.85,124.84 R262.2 ; v4(77.41,103.87) 77.41,103.82 78.36,102.87 78.36,101.31 77.83,100.78 77.83,98.51 77.98,98.36 77.98,94.46 78.99,93.45 78.99,76.68 77.72,75.41 77.72,72.39 78.87,71.25 v1(78.87,69.85)
D3: length 136
  TOP w0.102: U9.H4 74.89,103.39 73.67,103.39 73.28,103 73.28,101.98 v4(72.64,101.35) ; U16.D5 v5(66.79,72.16) ; v5(86.66,71.37) U15.N8
  TOP w0.127: CN11.32 v3(103.5,98.35)
  L3_SIG w0.102: v5(86.66,71.37) 86.48,71.37 86.11,70.99 85.72,70.99 85.47,70.74 85.47,69.95 85.06,69.55 79.2,69.55 78.99,69.34 74.93,69.34 v1(74.68,69.6) 74.15,69.6 74.05,69.7 74.05,69.8 73.95,69.9 73.74,69.9 73.64,69.8 73.64,69.7 73.54,69.6 73.34,69.6 73.23,69.7 73.23,69.8 73.13,69.9 72.93,69.9 72.83,69.8 72.83,69.7 72.73,69.6 72.52,69.6 72.42,69.7 72.42,69.8 72.32,69.9 72.12,69.9 72.01,69.8 72.01,69.7 71.91,69.6 71.71,69.6 71.61,69.7 71.61,69.8 71.51,69.9 71.3,69.9 71.2,69.8 71.2,69.7 71.1,69.6 70.9,69.6 70.8,69.7 70.8,69.8 70.69,69.9 70.49,69.9 70.39,69.8 70.39,69.7 70.29,69.6 70.08,69.6 69.98,69.7 69.98,69.8 69.88,69.9 69.68,69.9 69.58,69.8 69.58,69.7 69.47,69.6 69.27,69.6 69.17,69.7 69.17,69.8 69.07,69.9 68.87,69.9 68.76,69.8 68.76,69.7 68.66,69.6 68.3,69.6 67.18,70.71 67.18,71.77 v5(66.79,72.16) ; v4(72.64,101.35) 72.76,101.23 78.73,101.23 79.38,100.58 84.15,100.58 84.28,100.46 84.28,99.14 84.4,99.01 100.48,99.01 101.63,97.87 102.57,97.87 103.05,98.35 v3(103.5,98.35)
  BOTTOM w0.127: v4(72.64,101.35) 72.11,100.81 72.11,98.96 69.6,96.44 69.6,88.65 69.93,88.32 72.31,88.32 73.98,86.65 73.98,78.56 74.3,78.24 74.3,77.42 74.68,77.04 v1(74.68,69.6) ; v3(103.5,98.35) 102.95,97.79 101.84,97.79 101.49,98.14 101.49,98.26 87,112.75 87,121.34 86.81,121.52 85.11,121.52 R273.2
D4: length 126.9
  TOP w0.102: U9.H5 74.91,102.38 v4(74.42,102.87) ; v5(85.86,70.57) U15.P9 ; U16.E5 v5(65.29,72.16)
  TOP w0.127: CN10.11 v3(53.39,111.05) ; v1(64.52,121.28) R58.2
  L3_SIG w0.102: v4(74.42,102.87) 74.04,102.49 73.66,102.49 71.84,104.31 71.7,104.31 71.11,103.71 70.96,103.71 70.82,103.86 70.82,104 71.41,104.59 71.41,104.74 71.27,104.88 71.12,104.88 70.53,104.29 70.39,104.29 70.24,104.43 70.24,104.58 70.84,105.17 70.84,105.31 65.84,110.31 65.58,110.31 65.48,110.41 65.48,110.68 65.36,110.79 65.19,110.79 65.07,110.68 65.07,110.41 64.97,110.31 64.77,110.31 64.67,110.41 64.67,110.79 64.57,110.9 64.36,110.9 64.26,110.79 64.26,110.41 64.16,110.31 63.96,110.31 63.86,110.41 63.86,110.79 63.75,110.9 63.55,110.9 63.45,110.79 63.45,110.41 63.35,110.31 63.14,110.31 63.04,110.41 63.04,110.79 62.94,110.9 62.74,110.9 62.64,110.79 62.64,110.41 62.53,110.31 62.33,110.31 62.23,110.41 62.23,110.79 62.13,110.9 61.92,110.9 61.82,110.79 61.82,110.41 61.72,110.31 61.52,110.31 61.42,110.41 61.42,110.79 61.32,110.9 61.11,110.9 61.01,110.79 61.01,110.41 60.91,110.31 60.71,110.31 60.6,110.41 60.6,110.79 60.5,110.9 60.3,110.9 60.2,110.79 60.2,110.41 60.1,110.31 59.89,110.31 59.79,110.41 59.79,110.79 59.69,110.9 59.49,110.9 59.38,110.79 59.38,110.41 59.28,110.31 59.08,110.31 58.98,110.41 58.98,110.79 58.88,110.9 58.67,110.9 58.57,110.79 58.57,110.41 58.47,110.31 58.27,110.31 58.17,110.41 58.17,110.79 58.06,110.9 57.86,110.9 57.76,110.79 57.76,110.41 57.66,110.31 57.45,110.31 57.35,110.41 57.35,110.79 57.25,110.9 57.05,110.9 56.95,110.79 56.95,110.41 56.84,110.31 56.64,110.31 56.54,110.41 56.54,110.79 56.44,110.9 56.24,110.9 56.13,110.79 56.13,110.41 56.03,110.31 55.83,110.31 55.73,110.41 55.73,110.79 55.63,110.9 55.42,110.9 55.32,110.79 55.32,110.41 55.22,110.31 54.13,110.31 v3(53.39,111.05) ; v5(85.86,70.57) 85.86,69.91 85.19,69.24 82.63,69.24 82.53,69.14 82.53,68.78 82.43,68.68 82.23,68.68 82.13,68.78 82.13,69.14 82.02,69.24 81.82,69.24 81.72,69.14 81.72,68.78 81.62,68.68 81.41,68.68 81.31,68.78 81.31,69.14 81.21,69.24 81.01,69.24 80.91,69.14 80.91,68.78 80.81,68.68 80.6,68.68 80.5,68.78 80.5,69.14 80.4,69.24 80.2,69.24 80.09,69.14 80.09,68.78 79.99,68.68 79.79,68.68 79.69,68.78 79.69,69.14 79.59,69.24 79.32,69.24 79.04,68.96 77.6,68.96 77.55,68.91 v1(77.53,68.91) 77.48,68.96 68.5,68.96 65.78,71.69 65.76,71.69 v5(65.29,72.16)
  BOTTOM w0.127: v1(77.53,68.91) 77.22,69.23 77.22,71.28 76.52,71.98 76.52,92.06 72.54,96.04 72.54,96.85 73.89,98.2 73.89,102.34 v4(74.42,102.87) ; v1(64.52,121.28) 64.52,119.61 60.2,115.29 60.2,114.4 59.85,114.05 59.67,114.05 59.45,114.26 59.27,114.26 59.09,114.08 59.09,113.9 59.31,113.69 59.31,113.51 59.13,113.33 58.95,113.33 58.73,113.54 58.55,113.54 58.37,113.36 58.37,113.18 58.59,112.97 58.59,112.79 57.43,111.63 53.98,111.63 v3(53.39,111.05)
D5: length 133.4
  TOP w0.102: U9.E5 v4(77.41,102.87) ; U16.F5 v5(64.54,72.16) ; v5(87.46,71.37) U15.M8
  TOP w0.127: R50.2 v1(66.55,124.59) ; CN10.14 v3(54.81,109.78)
  L3_SIG w0.102: v5(64.54,72.16) 64.15,71.77 64.15,71.26 67.34,68.07 v1(78.49,68.07) 83.19,68.07 83.29,68.17 83.29,68.5 83.39,68.61 83.59,68.61 83.69,68.5 83.69,68.17 83.79,68.07 84,68.07 84.1,68.17 84.1,68.5 84.2,68.61 84.4,68.61 84.51,68.5 84.51,68.17 84.61,68.07 84.81,68.07 84.91,68.17 84.91,68.5 85.01,68.61 85.22,68.61 85.32,68.5 85.32,68.17 85.42,68.07 85.74,68.07 85.84,68.17 85.84,69.01 85.96,69.14 87.15,69.14 87.27,69.27 87.27,69.44 87.15,69.57 86.66,69.57 86.54,69.7 86.54,69.82 86.66,69.95 86.98,69.95 87.1,70.08 87.1,70.85 87.46,71.2 v5(87.46,71.37) ; v4(77.41,102.87) 76.5,102.87 75.85,102.22 73.29,102.22 72.39,103.12 71.07,103.12 69.1,105.09 69.1,105.23 69.57,105.7 69.57,105.84 69.43,105.99 69.28,105.99 68.82,105.52 68.67,105.52 68.53,105.66 68.53,105.81 69,106.27 69,106.42 68.85,106.56 68.71,106.56 68.24,106.09 68.1,106.09 67.95,106.24 67.95,106.38 68.42,106.85 68.42,106.99 68.28,107.14 68.13,107.14 67.67,106.67 67.52,106.67 67.38,106.81 67.38,106.96 67.85,107.42 67.85,107.57 67.7,107.71 67.56,107.71 67.09,107.24 66.95,107.24 66.8,107.39 66.8,107.53 67.27,108 67.27,108.14 67.13,108.29 66.98,108.29 66.52,107.82 66.37,107.82 66.23,107.96 66.23,108.11 66.7,108.57 66.7,108.72 66.55,108.86 66.41,108.86 65.94,108.4 65.8,108.4 65.65,108.54 65.65,108.68 66.12,109.15 66.12,109.29 65.98,109.44 65.83,109.44 65.37,108.97 65.22,108.97 65.08,109.11 65.08,109.26 65.55,109.72 65.55,109.87 65.4,110.01 65.26,110.01 64.79,109.55 64.65,109.55 64.41,109.78 v3(54.81,109.78)
  BOTTOM w0.127: v4(77.41,102.87) 77.82,102.46 77.82,101.7 76.96,100.85 76.96,98.96 77.6,98.33 77.6,94.28 78.61,93.27 78.61,76.83 77.34,75.56 77.34,72.23 78.11,71.47 78.11,69.72 78.49,69.34 v1(78.49,68.07) ; v3(54.81,109.78) 57.84,109.78 62.89,114.83 62.89,116.2 66.04,119.35 66.04,123.83 66.55,124.33 v1(66.55,124.59)
D6: length 130.6
  TOP w0.102: U9.H6 74.91,101.37 73.81,102.46 v4(73.81,102.89) ; v5(87.46,72.17) U15.M7 ; U16.F6 v5(64.54,71.41)
  TOP w0.127: R49.2 v1(65.53,124.59) ; CN10.12 v3(54.79,111.05)
  L3_SIG w0.102: v5(87.46,72.17) 87.01,71.72 87.01,71.22 86.72,70.92 86.51,70.92 86.23,70.65 86.23,69.85 85.29,68.91 83.01,68.91 82.88,68.78 82.88,68.5 82.75,68.38 78.89,68.38 78.69,68.58 77.98,68.58 77.77,68.38 76.96,68.38 v1(76.83,68.5) 67.44,68.5 64.54,71.4 v5(64.54,71.41) ; v4(73.81,102.89) 65.48,111.23 54.97,111.23 v3(54.79,111.05)
  BOTTOM w0.127: v1(65.53,124.59) 65.53,124.46 65.02,123.95 65.02,121.41 65.01,121.4 65.01,119.55 61.54,116.07 61.54,115.89 61.92,115.52 61.92,115.34 61.74,115.16 61.56,115.16 61.18,115.54 61,115.54 60.7,115.23 60.7,114.1 57.64,111.05 v3(54.79,111.05) ; v4(73.81,102.89) 73.56,102.64 73.56,98.42 72.14,97 72.14,95.89 76.14,91.88 76.14,71.82 76.83,71.12 76.83,69.95 76.71,69.82 75.36,69.82 75.23,69.7 75.23,69.52 75.36,69.39 76.45,69.39 76.58,69.27 76.58,68.99 76.45,68.86 74.3,68.86 74.17,68.99 74.17,69.55 74.05,69.67 73.79,69.67 73.66,69.55 73.66,68.3 73.54,68.17 73.28,68.17 73.15,68.3 73.15,69.55 73.03,69.67 72.85,69.67 72.72,69.55 72.72,67.84 72.85,67.72 73.93,67.72 74.06,67.84 74.06,68.3 74.19,68.43 74.44,68.43 74.57,68.3 74.57,67.82 74.7,67.69 74.95,67.69 75.08,67.82 75.08,68.3 75.2,68.43 76.76,68.43 v1(76.83,68.5)
D7: length 129
  TOP w0.102: v5(88.26,71.37) U15.L8 ; U9.E6 v4(77.41,101.87) ; U16.G6 v5(63.79,71.41)
  TOP w0.127: R59.2 v1(65.53,121.28) ; CN10.13 v3(53.39,109.78)
  L3_SIG w0.102: v4(77.41,101.87) 76.98,102.3 76.21,102.3 75.77,101.85 73.15,101.85 72.24,102.77 70.97,102.77 64.52,109.22 53.95,109.22 v3(53.39,109.78) ; v5(88.26,71.37) 87.88,70.99 87.88,69.42 86.99,68.53 86.85,68.53 86.55,68.83 86.38,68.83 86.26,68.71 86.26,68.54 86.56,68.24 86.56,68.1 86.08,67.61 77.5,67.61 v1(77.47,67.64) 67.34,67.64 63.79,71.19 v5(63.79,71.41)
  BOTTOM w0.127: v1(65.53,121.28) 65.53,119.43 62.36,116.26 62.36,115.06 57.78,110.49 54.1,110.49 v3(53.39,109.78) ; v4(77.41,101.87) 77.35,101.81 77.34,101.81 76.58,101.05 76.58,98.81 77.22,98.17 77.22,94.13 78.23,93.11 78.23,76.99 76.9,75.66 76.9,72.13 77.6,71.44 77.6,69.6 77.98,69.22 77.98,66.65 77.85,66.52 74.12,66.52 73.99,66.65 73.99,67.06 74.12,67.18 75.38,67.18 75.51,67.31 75.51,67.82 75.64,67.94 75.89,67.94 76.02,67.82 76.02,67.31 76.14,67.18 76.4,67.18 76.52,67.31 76.52,67.82 76.65,67.94 76.83,67.94 76.96,67.82 76.96,67.31 77.09,67.18 77.34,67.18 77.47,67.31 v1(77.47,67.64)
D8: length 139.7
  TOP w0.102: v4(72.01,102.36) 72.01,102.74 73.23,103.97 76.51,103.97 U9.F3 ; v5(67.94,76.07) 67.92,76.05 U16.B1 ; v5(88.26,76.97) U15.L2
  TOP w0.127: R51.2 v1(67.56,124.59) ; CN10.16 v3(54.86,108.51)
  L3_SIG w0.102: v3(54.86,108.51) 64.8,108.51 70.94,102.36 v4(72.01,102.36) ; v5(88.26,76.97) 87.88,76.59 87.88,75.87 87.62,75.61 84.66,75.61 84.15,76.12 82.68,76.12 82.3,75.74 74.35,75.74 v1(74.23,75.87) 74.15,75.79 70.33,75.79 69.65,75.11 67.45,75.11 67.35,75.01 67.35,74.87 67.24,74.77 67.04,74.77 66.94,74.87 66.94,75.01 66.84,75.11 66.64,75.11 66.53,75.01 66.53,74.87 66.43,74.77 66.23,74.77 66.13,74.87 66.13,75.01 66,75.13 65.83,75.13 65.71,75.01 65.71,74.75 65.58,74.63 65.38,74.63 65.25,74.75 65.25,75.29 65.38,75.41 67.44,75.41 67.56,75.54 67.56,75.95 67.69,76.07 v5(67.94,76.07)
  BOTTOM w0.127: v1(67.56,124.59) 67.06,124.08 67.06,118.95 65.67,117.56 65.67,117.38 66.09,116.96 66.09,116.78 65.91,116.61 65.73,116.61 65.31,117.02 65.13,117.02 64.92,116.81 64.92,116.64 65.34,116.22 65.34,116.01 57.84,108.51 v3(54.86,108.51) ; v1(74.23,75.87) 74.23,70.26 74.1,70.13 73,70.13 72.87,70.26 72.87,70.59 73,70.71 73.63,70.71 73.76,70.84 73.76,71.07 73.63,71.2 72.95,71.2 72.82,71.32 72.82,71.53 72.95,71.65 73.61,71.65 73.74,71.78 73.74,71.97 73.61,72.1 72.87,72.1 72.75,72.22 72.75,72.48 72.87,72.61 73.61,72.61 73.74,72.73 73.74,72.99 73.61,73.11 72.87,73.11 72.75,73.24 72.75,73.49 72.87,73.62 73.61,73.62 73.74,73.75 73.74,74 73.61,74.13 72.87,74.13 72.75,74.26 72.75,74.51 72.87,74.64 73.61,74.64 73.74,74.76 73.74,75.02 73.61,75.15 72.87,75.15 72.75,75.27 72.75,75.53 72.87,75.65 73.61,75.65 73.74,75.78 73.74,76.56 73.61,76.68 72.34,76.68 72.21,76.81 72.21,77.11 72.34,77.24 73.76,77.24 73.89,77.37 73.89,77.62 73.76,77.75 72.34,77.75 72.21,77.88 72.21,78.74 71.09,79.86 71.09,84.43 68.83,86.69 68.83,98.93 72.01,102.11 v4(72.01,102.36)
D9: length 137.6
  TOP w0.102: U16.C1 67.19,75.56 v5(67.19,76.07) ; 71.88,104.01 72.64,104.78 75.5,104.78 U9.G3 ; v5(87.46,76.17) U15.M3
  TOP w0.127: R60.2 v1(66.55,121.28) ; v1(71.03,101.77) 71.07,101.8 71.07,103.2 71.88,104.01 ; CN10.15 v3(53.42,108.51)
  L3_SIG w0.102: v1(71.03,101.77) 64.97,107.82 54.61,107.82 53.92,108.51 v3(53.42,108.51) ; v5(67.19,76.07) 67.19,75.88 67.01,75.69 65.41,75.69 65.28,75.82 65.28,76.23 65.51,76.45 69.01,76.45 69.14,76.33 69.14,75.84 69.01,75.72 67.95,75.72 67.84,75.61 67.84,75.47 67.95,75.36 69.45,75.36 69.57,75.48 69.57,76.35 69.67,76.45 69.87,76.45 69.98,76.35 69.98,76.2 70.08,76.1 70.28,76.1 70.38,76.2 70.38,76.35 70.48,76.45 70.69,76.45 70.82,76.33 70.82,76.2 70.94,76.07 71.12,76.07 71.25,76.2 71.25,76.33 71.37,76.45 71.55,76.45 71.78,76.23 v1(72.75,76.23) 73.71,76.23 73.84,76.35 74.45,76.35 74.75,76.05 82.14,76.05 82.52,76.43 84.3,76.43 84.91,75.81 87.1,75.81 v5(87.46,76.17)
  BOTTOM w0.127: v1(72.75,76.23) 72.34,75.82 72.34,68.53 72.21,68.4 70.36,68.4 70.23,68.53 70.23,68.78 70.36,68.91 71.65,68.91 71.78,69.04 71.78,69.24 71.65,69.37 70.36,69.37 70.23,69.49 70.23,69.75 70.36,69.88 71.68,69.88 71.81,70 71.81,70.26 71.68,70.38 70.38,70.38 70.26,70.51 70.26,70.76 70.38,70.89 71.7,70.89 71.83,71.02 71.83,78.56 70.54,79.86 70.54,84.43 68.45,86.51 68.45,99.21 71.01,101.77 v1(71.03,101.77) ; v3(53.42,108.51) 54,109.09 57.78,109.09 63.45,114.76 63.45,116.03 63.67,116.25 63.85,116.25 64.34,115.75 64.52,115.75 64.7,115.93 64.7,116.11 64.21,116.61 64.21,116.79 66.55,119.13 v1(66.55,121.28)
